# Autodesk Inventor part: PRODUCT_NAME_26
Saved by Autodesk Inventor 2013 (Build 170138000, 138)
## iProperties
Created: 2012-12
Part Number: PRODUCT_NAME_26
Material: Générique
Document SubType Name: Modeling
Designer: jost thierry
Density: 1 g/cm^3
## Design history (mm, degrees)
node "PRODUCT_NAME_261"
node "PRODUCT_NAME_26"
node "Base1"
